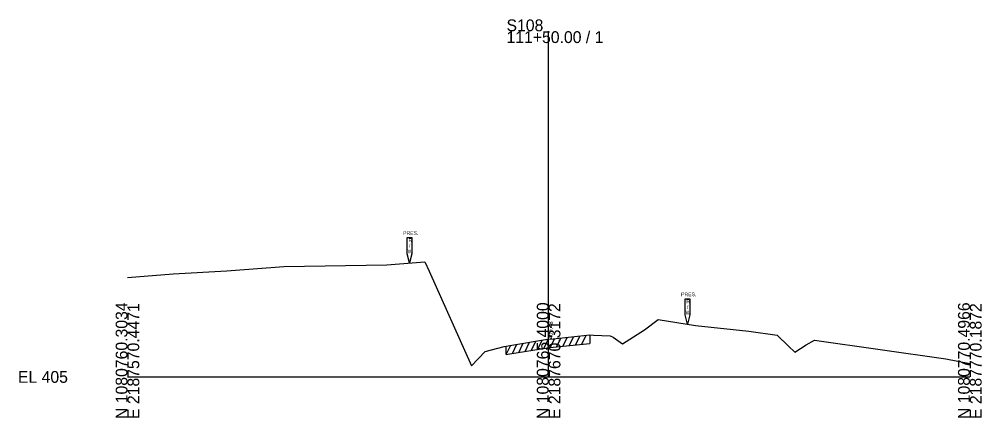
# Model space of a CAD drawing. Extents: x -26 to 2203, y 490 to 19581.
# Drawn here: x -25.7 to 202.8, y 16490.3 to 16584.9 of the extents above; entities that cross this region are included whole.
import ezdxf

# ---------------------------------------------------------------- set-up
doc = ezdxf.new("R2010")
doc.units = 0
for name, color, linetype in [('RD_GPK_XS_Cell', 7, 'Continuous'), ('RD_XS_ExGround', 7, 'Continuous'), ('RD_XS_ExPaveRet', 7, 'Continuous'), ('RD_XS_ExRW', 7, 'Continuous'), ('RD_XS_TX_Elev_EX', 7, 'Continuous')]:
    doc.layers.add(name, color=color, linetype=linetype)

msp = doc.modelspace()

# ---------------------------------------------------------------- linework, layer by layer
at = {"layer": 'RD_GPK_XS_Cell'}
for p, q in [((100, 16500), (100, 16582.05)), ((0, 16500), (100, 16500)), ((100, 16500), (200, 16500))]:
    msp.add_line(p, q, dxfattribs=at)
at = {"layer": 'RD_XS_ExGround'}
msp.add_lwpolyline([(0, 16523.56), (10.85, 16524.45), (23.61, 16525.14), (37.15, 16526.24), (61.58, 16526.62), (70.58, 16527.35), (71.65, 16525.08), (81.67, 16502.6), (84.93, 16506.05), (89.41, 16507.18), (89.9, 16507.32), (90.79, 16507.47), (99.74, 16508.93), (101.09, 16509.07), (109.75, 16509.95), (110.69, 16509.87), (114.65, 16509.77), (115.32, 16509.47), (117.58, 16507.86), (122.8, 16511.17), (126.04, 16513.6), (134.9, 16512.22), (147.57, 16510.84), (154.28, 16509.87), (156.92, 16507.28), (158.44, 16505.9), (161.18, 16507.61), (163.11, 16508.72), (178.71, 16506.51), (194.28, 16504.31), (200, 16503.16)], dxfattribs=at)
at = {"layer": 'RD_XS_ExPaveRet'}
for p, q in [((101.9, 16507.15), (102.95, 16509.26)), ((103.4, 16507.3), (104.45, 16509.41)), ((104.9, 16507.46), (105.95, 16509.56)), ((106.4, 16507.61), (107.45, 16509.72)), ((107.9, 16507.76), (108.95, 16509.87)), ((109.75, 16509.95), (109.75, 16507.95)), ((89.9, 16505.32), (90.99, 16507.51)), ((89.9, 16505.32), (89.9, 16507.32)), ((90.79, 16505.47), (99.74, 16506.93)), ((91.4, 16505.57), (92.49, 16507.75)), ((92.9, 16505.82), (93.99, 16507.99)), ((94.4, 16506.06), (95.49, 16508.24)), ((95.9, 16506.31), (96.99, 16508.48)), ((97.4, 16506.55), (98.49, 16508.73)), ((98.9, 16506.79), (99.98, 16508.96)), ((99.74, 16506.93), (101.09, 16507.07)), ((100.4, 16507), (101.45, 16509.11)), ((101.09, 16507.07), (109.75, 16507.95)), ((89.9, 16505.32), (90.79, 16505.47))]:
    msp.add_line(p, q, dxfattribs=at)
at = {"layer": 'RD_XS_ExRW'}
for points in [[(66.45, 16533.08), (67.55, 16533.08), (67.55, 16529.25), (67, 16527.06), (66.45, 16529.25)], [(132.45, 16518.53), (133.55, 16518.53), (133.55, 16514.7), (133, 16512.51), (132.45, 16514.7)]]:
    msp.add_lwpolyline(points, close=True, dxfattribs=at)

# ---------------------------------------------------------------- texts
at = {"layer": 'RD_GPK_XS_Cell'}
for s, p in [('S108', (90, 16582.05)), ('111+50.00 / 1', (90, 16579.25)), ('EL 405', (-26, 16498.6))]:
    msp.add_text(s, height=2.8, dxfattribs=at).set_placement(p)
for s, p in [('N 1080760.3034', (0, 16490)), ('E 2187570.4471', (2.8, 16490)), ('N 1080765.4000', (100, 16490)), ('E 2187670.3172', (102.8, 16490)), ('N 1080770.4966', (200, 16490)), ('E 2187770.1872', (202.8, 16490))]:
    msp.add_text(s, height=2.8, rotation=90, dxfattribs=at).set_placement(p)
at = {"layer": 'RD_XS_ExRW'}
for s, p in [('PRES.', (65.45, 16533.7)), ('R', (66.71, 16531.99)), ('W', (66.53, 16529.36)), ('/', (66.83, 16530.67)), ('PRES.', (131.45, 16519.16)), ('R', (132.71, 16517.44)), ('/', (132.83, 16516.13)), ('W', (132.53, 16514.81))]:
    msp.add_text(s, height=0.875, dxfattribs=at).set_placement(p)
at = {"layer": 'RD_XS_TX_Elev_EX'}
msp.add_text('409.48', height=1, rotation=90, dxfattribs=at).set_placement((101, 16508.96))

doc.saveas('drawing.dxf')
